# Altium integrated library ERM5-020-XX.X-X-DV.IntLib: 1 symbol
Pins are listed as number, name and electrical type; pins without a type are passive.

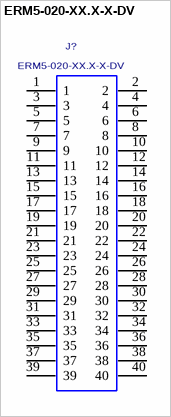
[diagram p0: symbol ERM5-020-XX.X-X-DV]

## ERM5-020-XX.X-X-DV
designator J?
Terminal Assembly, Double Row Vertical, Surface Mount, 0.5mm Pitch, 40 Pins; MANUFACTURER: SAMTEC
footprint ERM5-020-XX.X-X-DV
pins: 1, 2, 3, 4, 5, 6, 7, 8, 9, 10, 11, 12, 13, 14, 15, 16, 17, 18, 19, 20, 21, 22, 23, 24, 25, 26, 27, 28, 29, 30, 31, 32, 33, 34, 35, 36, 37, 38, 39, 40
